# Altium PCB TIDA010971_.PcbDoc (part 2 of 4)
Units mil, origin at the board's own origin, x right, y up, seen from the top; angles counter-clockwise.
Board outline 4500 x 6000 mil, 2 copper layers (F.CU, B.CU), stack 60.617 mil thick; 280 components, 124 nets, 681 pads, 871 vias.
Unrouted connection lines stored in the file: 1.
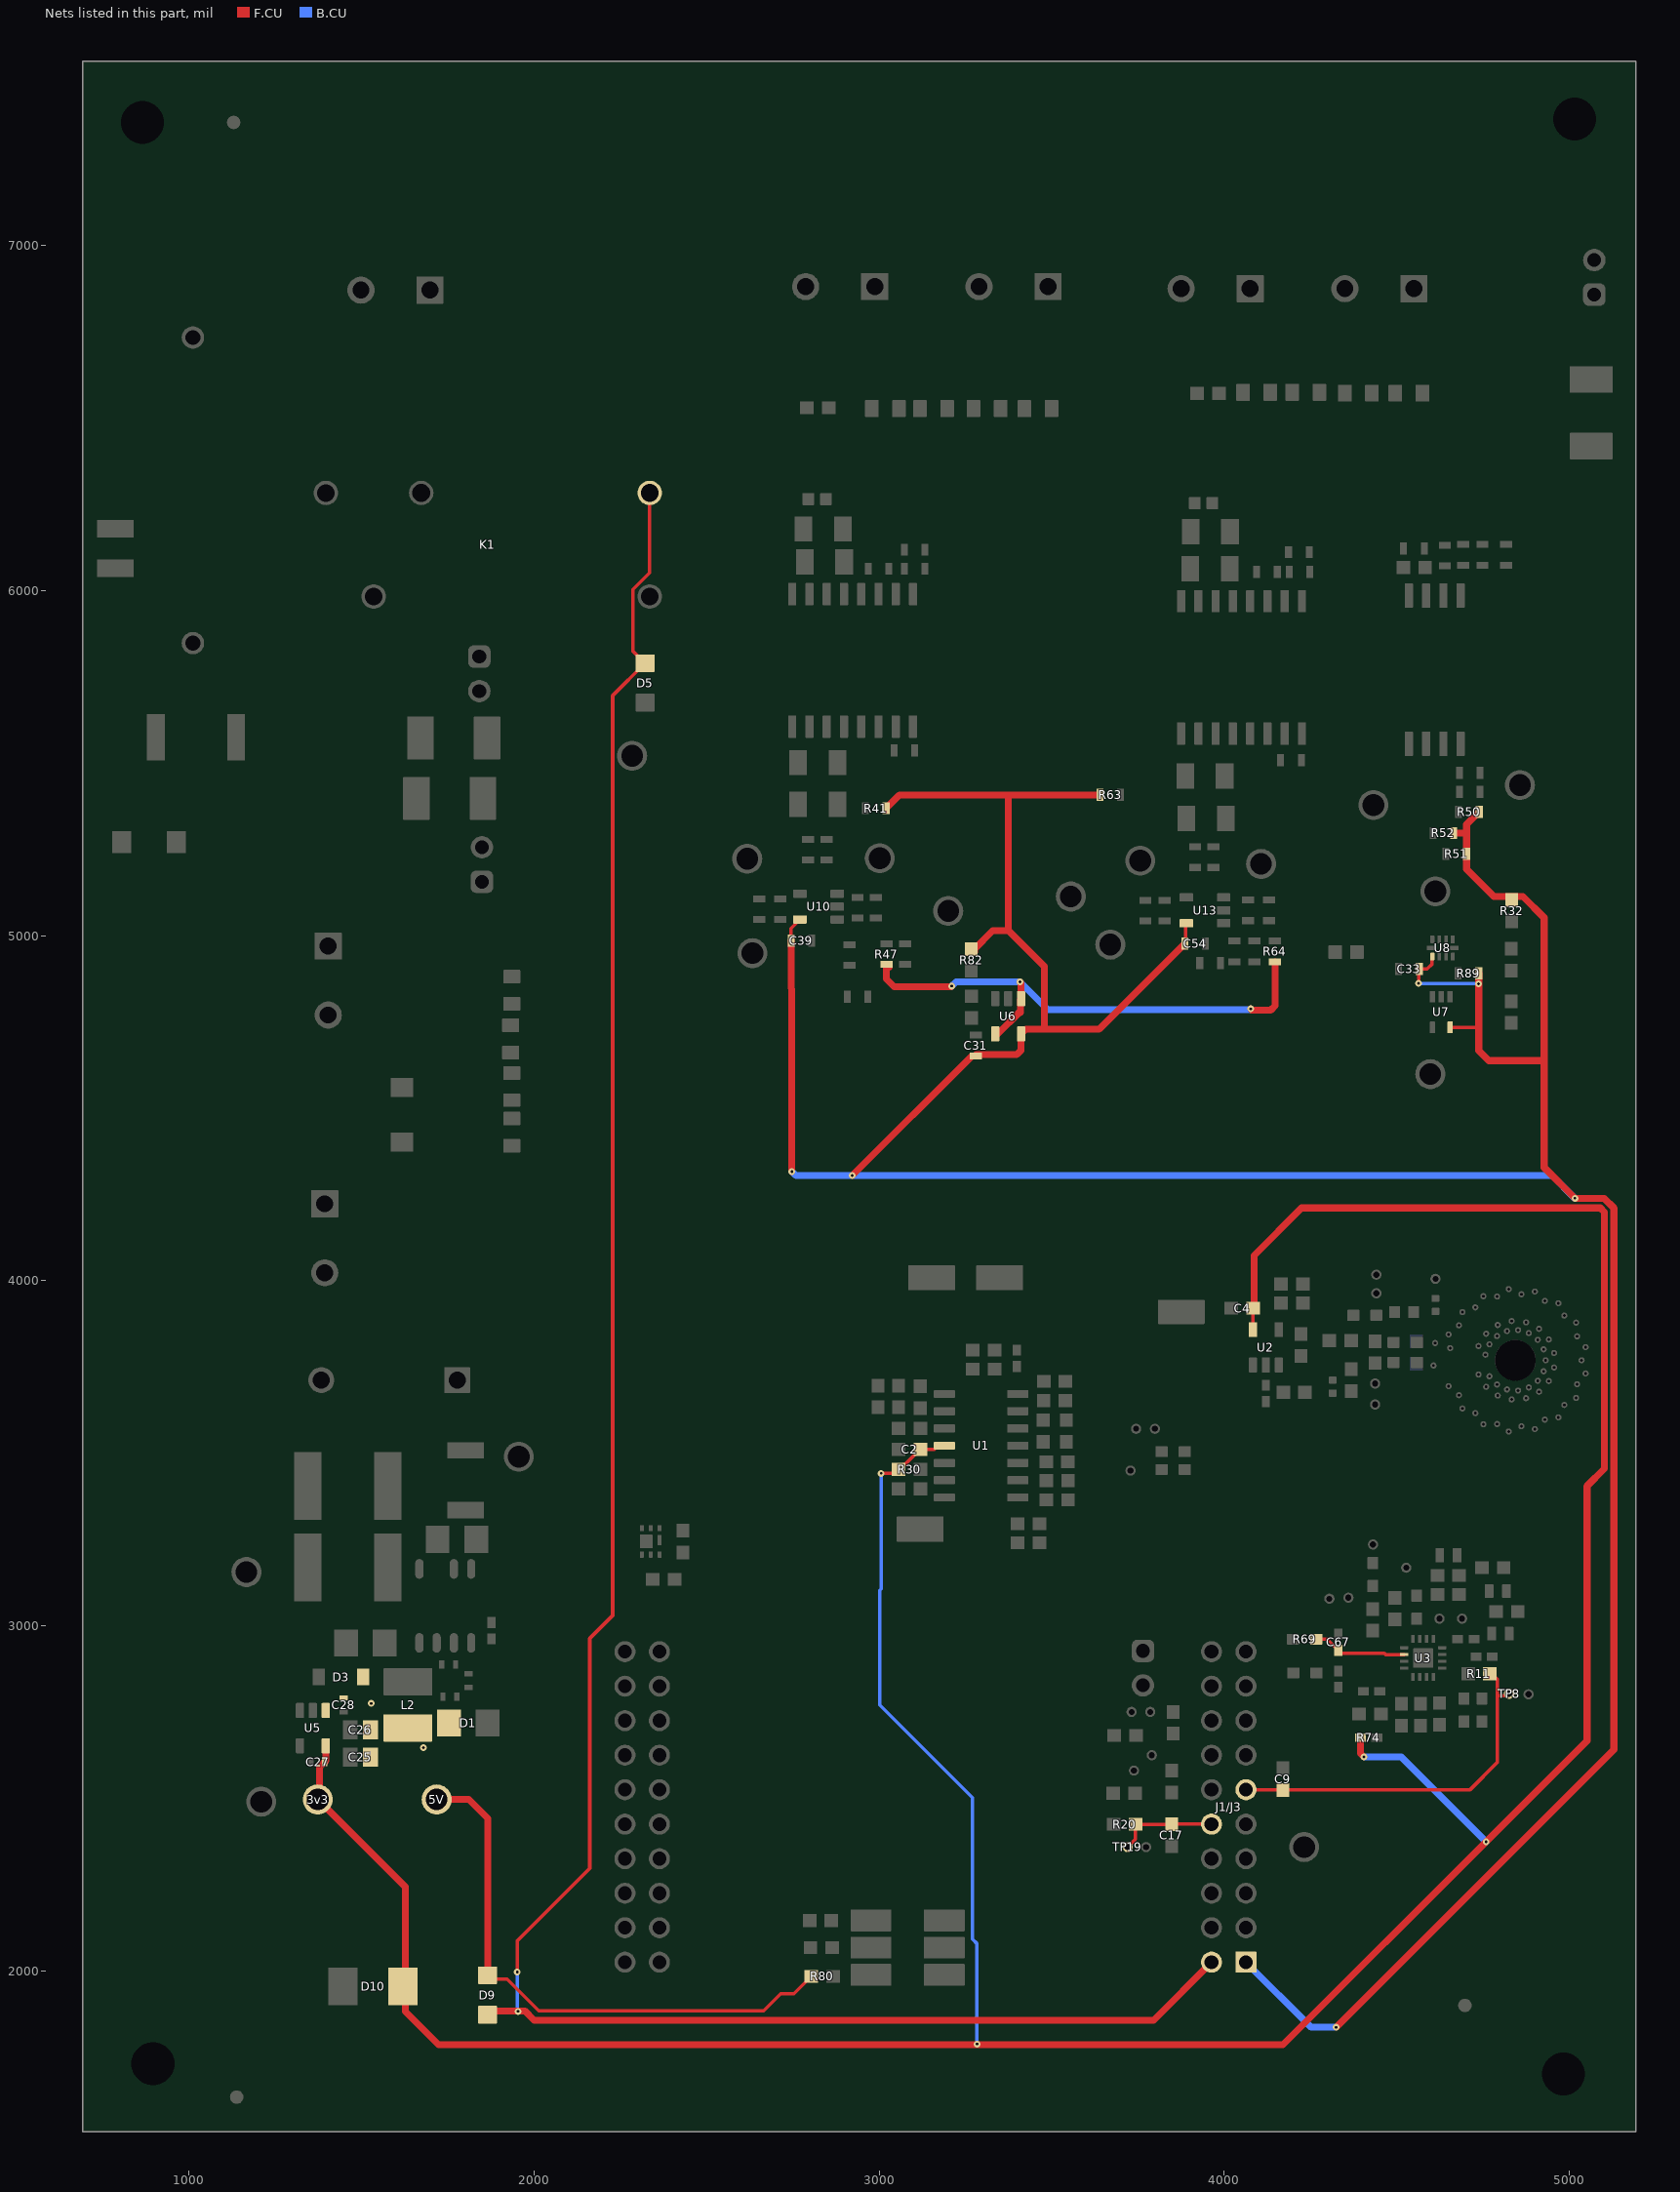
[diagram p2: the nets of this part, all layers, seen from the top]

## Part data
1 AGND3 TP_VIN: library part CMP-0089962-1, "Natural PC Test Point Brass, Tin Plating Surface Mount Mounting Type", Current_A=2A, Digikey Part Number=952-1478-1-ND, Manufacturer=Harwin, Mouser Part Number=855-S1751-46R, Operating Temperature Range="-55°C to +125°C"
3v3 5V Primary: library part CMP-0055147-2, "Test Point, Multipurpose, Red, TH", Color=Red, Manufacturer="Keystone Electronics", Supplier Part Number 1=36-5010-ND
AGND2: library part CMP-0055143-2, "Test Point, Compact, Black, TH", Color=Black, Manufacturer="Keystone Electronics", PartNumber=5006, Supplier Part Number 1=36-5006-ND
C1 C10: library part CMP-0007159-4, "CAP, CERM, 1000 pF, 25 V, +/- 5%, C0G/NP0, 0603", Cap_Case=0603, Manufacturer=MuRata, Supplier Part Number 1=GRM1885C1E102JA01D-ND, TempCo=C0G/NP0, Tolerance_%=5%, Value1=Unknown, Value2=25V, ValueDisplayed=1000pF
C2 C4 C13: library part CMP-0006815-4, "CAP, CERM, 0.1 uF, 10 V, +/- 10%, X7R, 0603", Cap_Case=0603, Manufacturer=AVX, Supplier Part Number 1=478-7939-1-ND, TempCo=X7R, Tolerance_%=10%, Value1=Unknown, Value2=10V, ValueDisplayed=0.1uF
C3 C32: library part CMP-0093200-1, "1µF ±10% 10V Ceramic Capacitor X7R 0402 (1005 Metric)", Digikey Part Number=2571-GMC04X7R105K10NTTR-ND, Manufacturer="Cal-Chip Electronics", Operating Temperature Range="-55°C to +125°C", TempCo=15%, Temperature Characteristic=X7R, Tolerance_%=10%, ValueDisplayed=1uF
C5 C11: library part CMP-0006910-4, "CAP, CERM, 270 pF, 50 V, +/- 5%, C0G/NP0, 0603", Cap_Case=0603, Manufacturer=Kemet, Supplier Part Number 1=399-1067-1-ND, TempCo=C0G/NP0, Tolerance_%=5%, Value1=Unknown, Value2=50V, ValueDisplayed=270pF
C6 C7 C19: library part CMP-0006763-4, "CAP, CERM, 100 pF, 50 V, +/- 5%, C0G/NP0, 0603", Cap_Case=0603, Manufacturer=AVX, Supplier Part Number 1=478-1175-1-ND, TempCo=C0G/NP0, Tolerance_%=5%, Value1="0.119 ohm", Value2=50V, ValueDisplayed=100pF
C8: library part CMP-0083854-1, "CAP, CERM, 0.1 µF, 50 V,+/- 5%, X7R, 0603", Cap_Case=0603, Manufacturer=AVX, TempCo=X7R, Tolerance_%=5%, Value2=50V, ValueDisplayed=0.1µF
C9 C17 C30: library part CMP-0007220-4, "CAP, CERM, 47 pF, 50 V, +/- 5%, C0G/NP0, 0603", Cap_Case=0603, Manufacturer=MuRata, Supplier Part Number 1=490-1419-1-ND, TempCo=C0G/NP0, Tolerance_%=5%, Value1=Unknown, Value2=50V, ValueDisplayed=47pF
C12: library part CMP-0007182-4, "CAP, CERM, 130 pF, 50 V, +/- 5%, C0G/NP0, 0603", Cap_Case=0603, Manufacturer=MuRata, Supplier Part Number 1=490-1430-1-ND, TempCo=C0G/NP0, Tolerance_%=5%, Value1=Unknown, Value2=50V, ValueDisplayed=130pF
C14: library part CMP-0007186-4, "CAP, CERM, 1500 pF, 50 V, +/- 5%, C0G/NP0, 0603", Cap_Case=0603, Manufacturer=MuRata, Supplier Part Number 1=490-1455-1-ND, TempCo=C0G/NP0, Tolerance_%=5%, Value1=Unknown, Value2=50V, ValueDisplayed=1500pF
C15: library part CMP-0006789-4, "CAP, CERM, 47 pF, 50 V, +/- 5%, C0G/NP0, 0603", Cap_Case=0603, Manufacturer=AVX, Supplier Part Number 1=478-1171-1-ND, TempCo=C0G/NP0, Tolerance_%=5%, Value1="0.174 ohm", Value2=50V, ValueDisplayed=47pF
C16 C70: library part CMP-0085576-2, "CAP, CERM, 3900 pF, 50 V,+/- 10%, X7R, 0402", Cap_Case=0402, Manufacturer="Samsung Electro-Mechanics", TempCo=X7R, Tolerance_%=10%, Value2=50V, ValueDisplayed=3900pF
C18: library part CMP-0007209-4, "CAP, CERM, 330 pF, 50 V, +/- 5%, C0G/NP0, 0603", Cap_Case=0603, Manufacturer=MuRata, Supplier Part Number 1=490-1439-1-ND, TempCo=C0G/NP0, Tolerance_%=5%, Value1=Unknown, Value2=50V, ValueDisplayed=330pF
C20: library part CMP-0006679-2, "CAP, CERM, 0.015 uF, 50 V, +/- 10%, X7R, 0402", Cap_Case=0402, Manufacturer=MuRata, Supplier Part Number 1=490-4517-1-ND, TempCo=X7R, Tolerance_%=10%, Value1=Unknown, Value2=50V, ValueDisplayed=0.015uF
C21: library part CMP-0084375-1, "CAP, CERM, 1 µF, 16 V,+/- 20%, X5R, 0402", Cap_Case=0402, Manufacturer=MuRata, TempCo=X5R, Tolerance_%=20%, Value2=16V, ValueDisplayed=1µF
C22 C23: library part CMP-0009428-2, "CAP, CERM, 2.2 uF, 450 V, +/- 20%, X7T, AEC-Q200 Grade 1, 6x5x5mm", Cap_Case=2220, Manufacturer=TDK, Supplier Part Number 1=445-7109-1-ND, TempCo=X7T, Tolerance_%=20%, Value1=Unknown, Value2=450V, ValueDisplayed=2.2uF
C24: library part CMP-0006449-2, "CAP, CERM, 2.4 pF, 50 V, +/- 5%, C0G/NP0, 0402", Cap_Case=0402, Manufacturer=MuRata, Supplier Part Number 1=81-GRM1555C1H2R4CA1D, TempCo=C0G/NP0, Tolerance_%=5%, Value1=Unknown, Value2=50V, ValueDisplayed=2.4pF
C25 C26: library part CMP-0078699-1, "CAP, CERM, 47 µF, 10 V,+/- 20%, X5R, 0805", Cap_Case=0805, Manufacturer=MuRata, Supplier Part Number 1=490-9961-1-ND, TempCo=X5R, Tolerance_%=20%, Value2=10V, ValueDisplayed=47µF
C27: library part CMP-0064927-2, "CAP, CERM, 1 uF, 10 V,+/- 20%, X5R, 0402", Cap_Case=0402, Manufacturer=MuRata, Supplier Part Number 1=490-5409-1-ND, TempCo=X5R, Tolerance_%=20%, Value1=Unknown, Value2=10V, ValueDisplayed=1uF
C28: library part CMP-0006562-2, "CAP, CERM, 0.1 uF, 10 V, +/- 10%, X5R, 0402", Cap_Case=0402, Manufacturer=MuRata, Supplier Part Number 1=490-1318-1-ND, TempCo=X5R, Tolerance_%=10%, Value1=Unknown, Value2=10V, ValueDisplayed=0.1uF
C29: library part CMP-0007109-5, "CAP, CERM, 0.01 uF, 50 V, +/- 10%, X7R, 0603", Cap_Case=0603, Manufacturer="Samsung Electro-Mechanics", Supplier Part Number 1=1276-1921-1-ND, TempCo=X7R, Tolerance_%=10%, Value1=Unknown, Value2=50V, ValueDisplayed=0.01uF
C31 C37 C38 C58 C59: library part CMP-0079602-1, "CAP, CERM, 0.1 µF, 50 V,+/- 10%, X7R, AEC-Q200 Grade 1, 0603", Cap_Case=0603, Manufacturer=Kemet, Supplier Part Number 1=399-6856-1-ND, TempCo=X7R, Tolerance_%=10%, Value2=50V, ValueDisplayed=0.1µF
C33: library part CMP-0006856-6, "CAP, CERM, 0.1 uF, 25 V, +/- 5%, X7R, 0603", Cap_Case=0603, Manufacturer=Kemet, Supplier Part Number 1=399-1282-1-ND, TempCo=X7R, Tolerance_%=5%, Value1=Unknown, Value2=25V, ValueDisplayed=0.1uF
C34 C47 C50 C55: library part CMP-0006754-4, "CAP, CERM, 1 uF, 25 V, +/- 10%, X7R, 0603", Cap_Case=0603, Manufacturer=AVX, Supplier Part Number 1=478-10046-1-ND, TempCo=X7R, Tolerance_%=10%, Value1=Unknown, Value2=25V, ValueDisplayed=1uF
C35 C56: library part CMP-0006847-4, "CAP, CERM, 1000 pF, 50 V, +/- 10%, X7R, 0603", Cap_Case=0603, Manufacturer=Kemet, Supplier Part Number 1=399-1082-1-ND, TempCo=X7R, Tolerance_%=10%, Value1=Unknown, Value2=50V, ValueDisplayed=1000pF
C36 C45 C46 C51 C57 C60: library part CMP-0007114-5, "CAP, CERM, 1000 pF, 50 V, +/- 5%, X7R, 0603", Cap_Case=0603, Manufacturer="Samsung Electro-Mechanics", Supplier Part Number 1=1276-1091-1-ND, TempCo=X7R, Tolerance_%=5%, Value1=Unknown, Value2=50V, ValueDisplayed=1000pF
C39 C54: library part CMP-0006855-4, "CAP, CERM, 0.1 uF, 25 V, +/- 5%, X7R, 0603", Cap_Case=0603, Manufacturer=Kemet, Supplier Part Number 1=1650833, TempCo=X7R, Tolerance_%=5%, Value1=Unknown, Value2=25V, ValueDisplayed=0.1uF
C40 C61: library part CMP-0045719-1, "1000 pF ±10% 50V Ceramic Capacitor X7R 0603 (1608 Metric)", Digikey Part Number=399-C0603X102K5RAC7867CT-ND, Manufacturer=KEMET, Mouser Part Number=80-C0603X102K5R, Operating Temperature Range="-55°C to +125°C", TempCo=15%, Temperature Characteristic=X7R, Tolerance_%=10%, ValueDisplayed=1000pF
C41 C43 C62 C64: library part CMP-0008530-2, "CAP, CERM, 1000 pF, 50 V, +/- 10%, X7R, 1206", Cap_Case=1206, Manufacturer=AVX, Supplier Part Number 1=478-1530-1-ND, TempCo=X7R, Tolerance_%=10%, Value1="0.427 ohm", Value2=50V, ValueDisplayed=1000pF
C42 C63: library part CMP-0008586-2, "CAP, CERM, 0.1 uF, 50 V, +/- 10%, X7R, 1206", Cap_Case=1206, Manufacturer=Kemet, Supplier Part Number 1=399-1249-1-ND, TempCo=X7R, Tolerance_%=10%, Value1="0.059 ohm", Value2=50V, ValueDisplayed=0.1uF
C44 C65: library part CMP-0008509-2, "CAP, CERM, 1 uF, 25 V, +/- 10%, X7R, 1206", Cap_Case=1206, Manufacturer=AVX, Supplier Part Number 1=478-1567-1-ND, TempCo=X7R, Tolerance_%=10%, Value1="0.013 ohm", Value2=25V, ValueDisplayed=1uF
C48 C49 C53: library part CMP-0006753-4, "CAP, CERM, 0.1 uF, 25 V, +/- 10%, X7R, 0603", Cap_Case=0603, Manufacturer=AVX, Supplier Part Number 1=478-3714-1-ND, TempCo=X7R, Tolerance_%=10%, Value1="0.05 ohm", Value2=25V, ValueDisplayed=0.1uF
C52: library part CMP-0006839-4, "CAP, CERM, 10 pF, 50 V, +/- 5%, C0G/NP0, 0603", Cap_Case=0603, Manufacturer=Kemet, Supplier Part Number 1=399-1049-1-ND, TempCo=C0G/NP0, Tolerance_%=5%, Value1=Unknown, Value2=50V, ValueDisplayed=10pF
C66 C67: library part CMP-0860544-1, "CAP, CERM, 0.01 µF, 6.3 V,+/- 10%, X7R, 0402", Cap_Case=0402, Manufacturer=Walsin, TempCo=X7R, Tolerance_%=10%, Value2=6.3V, ValueDisplayed=0.01µF
C68: library part CMP-0007497-5, "CAP, CERM, 10 uF, 10 V, +/- 20%, X7R, 0603", Cap_Case=0603, Manufacturer=MuRata, Supplier Part Number 1=81-GRM188Z71A106MA3D, TempCo=X7R, Tolerance_%=20%, Value1=Unknown, Value2=10V, ValueDisplayed=10uF
C69: library part CMP-0006622-2, "CAP, CERM, 0.01 uF, 6.3 V, +/- 10%, X7R, 0402", Cap_Case=0402, Manufacturer=MuRata, Supplier Part Number 1=GRM155R70J103KA01D-ND, TempCo=X7R, Tolerance_%=10%, Value1=Unknown, Value2=6.3V, ValueDisplayed=0.01uF
C71: library part CMP-0077664-2, "CAP, Film, 0.1 µF, X2 305 VAC, +/- 10%, AEC-Q200 Grade 2, TH", Manufacturer=TDK, Supplier Part Number 1=495-4355-ND, Tolerance_%=10%, ValueDisplayed=0.1µF
C72: library part CMP-0081059-1, "CAP, CERM, 1000 pF, 25 V,+/- 5%, C0G/NP0, 0402", Cap_Case=0402, Manufacturer=Kemet, Supplier Part Number 1=399-7751-1-ND, TempCo=C0G/NP0, Tolerance_%=5%, Value2=25V, ValueDisplayed=1000pF
CTR: library part CMP-0055142-2, "Test Point, Compact, Red, TH", Color=Red, Manufacturer="Keystone Electronics", PartNumber=5005, Supplier Part Number 1=36-5005-ND
D1 D2 D4: library part CMP-0029015-1, "Diode, Ultrafast, 600 V, 1 A, 1408 Diode", Manufacturer=Bourns, Supplier Part Number 1=CD1408-FU1600CT-ND, Value1=1A, Value2=1.25V
D3: library part CMP-0085110-1, "Diode, Zener, 8.2 V, 500 mW, SOD-123", Manufacturer="Diodes Inc.", Power_W=500mW, Value1=0.5W
D5 D9: library part CMP-0028636-3, "Diode, Schottky, 20 V, 1.1 A, DO-219AB", Manufacturer=Vishay-Semiconductor, PartNumber=SL02-GS08, Value1=1.1A, Value2=0.42V
D6: library part CMP-0078806-2, "LED, RGB, SMD", Color=RGB, Manufacturer=Kingbright, Power_TotalModule=350mW, Value1=0.35W, Value2=3.3V
D7 D8: library part CMP-0085045-1, "Diode, TVS, Bi, 400 V, 648 Vc, 400 W, 0.6 A, SMA (non-polarized)", Manufacturer=Littelfuse, Value1=648V
D10: library part CMP-0005592-3, "Diode, TVS, Uni, 3.3 V, 7.3 Vc, AEC-Q101, SMB", Manufacturer=Vishay-Semiconductor, Value1=600W
F1 F2 F3: library part CMP-0121481-1, "5 A 250 V AC 125 V DC Fuse Board Mount (Cartridge Style Excluded) Surface Mount 2-SMD, Square End Block", Digikey Part Number=F6636CT-ND, Fuse Current=5A, Fuse Interrupt Dc Current=300A, Manufacturer=Littelfuse, Mouser Part Number=576-0476005.MR, Operating Temperature Range="-55°C to +125°C"
FID1 FID2 FID3: library part CMP-0077181-1, "Fiducial mark.  There is nothing to buy or mount.", Manufacturer=N/A
GND Neutral: library part CMP-0055148-2, "Test Point, Multipurpose, Black, TH", Color=Black, Manufacturer="Keystone Electronics", Supplier Part Number 1=36-5011-ND
J1 J7 J12 J13: library part CMP-0075405-2, "Header, 100mil, 2x1, Gold, TH", Color=Black, Current_A=6.3A, Manufacturer=Samtec, Supplier Part Number 1=SAM1029-02-ND, Voltage_V=550V
J1/J3: library part CMP-0003837-4, "Receptacle, 2.54mm, 10x2, Tin, TH", Alternate Manufacturer="Major League Electronics", Alternate PartNumber=CRD-081413-A-G, Manufacturer=Samtec, Supplier Part Number 1=SAM1204-10-ND
J2 J3 J4 J5 J6 J8 J9: library part CMP-0074910-1, "Terminal Block, 5.08 mm, 2x1, Brass, TH", Color=Blue, Current_A=15A, Manufacturer="On-Shore Technology", Supplier Part Number 1=ED1609-ND, Voltage_V=300V
J2/J4: library part CMP-0078266-4, "Receptacle, 2.54mm, 10x2, Tin, TH", Alternate Manufacturer="Major League Electronics", Alternate PartNumber=CRD-081413-A-G, Manufacturer=Samtec, Supplier Part Number 1=SAM1204-10-ND
K1: library part CMP-0002574-2, "Relay, SPDT ( 1 Form C), 12 A, 5 V, TH", Coil Current_A=80mA, Coil Power_W=403mW, Coil Resistance_ohm=62, Coil Voltage_VDC=5V, Contact Rating_A=12A, Manufacturer="Tyco Electronics", Supplier Part Number 1=PB359-ND, Turn Off Voltage (Min)_VDC=5dV, Turn On Voltage (Max)_VDC=3.5V
L1: library part CMP-0058731-1, "Inductor, Multilayer, Ferrite, 10 uH, 0.05 A, 0.9 ohm, SMD", Manufacturer=MuRata, Supplier Part Number 1=490-4025-1-ND, Value1="0.9 ohm", Value2=0.05A, ValueDisplayed=10uH
L2: library part CMP-0084743-1, "Inductor, Wirewound, Ferrite, 680 µH, 0.09 A, 16.8 ohm, SMD", Manufacturer="Wurth Elektronik", Value1="16.8 ohm", Value2=0.09A, ValueDisplayed=680µH
L3: library part CMP-0060129-1, "Inductor, Wirewound, Ferrite, 820 nH, 0.42 A, 0.579999 ohm, SMD", Manufacturer=Coilcraft, Value1="0.579999 ohm", Value2=0.42A, ValueDisplayed=820nH
L4: library part CMP-0077489-1, "Inductor, Wirewound, Ferrite, 3.9 µH, 0.28 A, 1.6 ohm, AEC-Q200 Grade 3, SMD", Manufacturer=Coilcraft, Supplier Part Number 1=994-0603LS-392XJLB, Value1="1.6 ohm", Value2=0.28A, ValueDisplayed=3.9µH
L5: library part CMP-0077486-1, "Inductor, Wirewound, Ferrite, 330 nH, 0.56 A, 0.46 ohm, AEC-Q200 Grade 3, SMD", Manufacturer=Coilcraft, Supplier Part Number 1=994-0603LS-331XJLB, Value1="0.46 ohm", Value2=0.56A, ValueDisplayed=330nH
Logo1: library part CMP-0074838-1, "Texas Instrument Corporate Signature"
Logo2: library part CMP-0074844-1
Logo3: library part CMP-0074847-1, "FCC_disclaimer"
Logo4: library part CMP-0074769-1
LOGO5 LOGO6 LOGO8 LOGO10: library part CMP-0074835-1, "IEC 61010-1 High Voltage Warning"
LOGO7 LOGO9: library part CMP-0074837-1, "IEC 61010-1 Hot Surface Warning"
MH1 MH2 MH3 MH4: library part CMP-0078424-2, "PCB Mounting Hole, No Pad", Manufacturer=Any, PartNumber=N/A
MP1 MP2 MP3 MP4: library part CMP-0122442-1, "Hex Standoff Threaded #4-40 Nylon 1.000\" (25.40mm) 1\" Natural", Digikey Part Number=36-4806-ND, Manufacturer=Keystone, Mouser Part Number=534-4806, Operating Temperature Range=to
Q1: library part CMP-0000193-1, "MOSFET, N-CH, 12 V, 22 A, DQK0006C (WSON-6)", Alternate Manufacturer=None, Manufacturer="Texas Instruments", Supplier Part Number 1=CSD13202Q2-ND, Value1=0.009, Value2="5.1 nC"
R1: library part CMP-0023953-2, "RES, 221, 0.1%, 0.1 W, 0603", Manufacturer="Yageo America", Power_W=100mW, TempCo="25 ppm/C", Tolerance_%=0.1%, Value2=0.1W, Value_Code=221R, ValueDisplayed=221
R2 R4: library part CMP-0022004-4, "RES, 10.0, 1%, 0.25 W, AEC-Q200 Grade 0, 0603", Manufacturer=Vishay-Dale, Power_W=250mW, Supplier Part Number 1=541-10.0SCT-ND, TempCo="100 ppm/C", Tolerance_%=1%, Value2=0.25W, Value_Code=10R0, ValueDisplayed=10.0
R3: library part CMP-0023468-3, "RES, 221, 0.1%, 0.1 W, 0603", Manufacturer="Susumu Co Ltd", Power_W=100mW, Supplier Part Number 1=RG16P221BCT-ND, TempCo="25 ppm/C", Tolerance_%=0.1%, Value2=0.1W, Value_Code=221R, ValueDisplayed=221
R5: library part CMP-0025335-3, "RES, 4.02 k, 0.5%, 0.1 W, 0603", Manufacturer="Yageo America", Power_W=100mW, TempCo="50 ppm/C", Tolerance_%=0.5%, Value2=0.1W, Value_Code=4k02, ValueDisplayed=4.02k
R6: library part CMP-0024341-3, "RES, 562 k, 0.1%, 0.1 W, 0603", Manufacturer="Yageo America", Power_W=100mW, TempCo="25 ppm/C", Tolerance_%=0.1%, Value2=0.1W, Value_Code=562k
R7: library part CMP-0023646-2, "RES, 10.1 k, 0.1%, 0.1 W, 0603", Manufacturer="Yageo America", Power_W=100mW, TempCo="25 ppm/C", Tolerance_%=0.1%, Value2=0.1W, Value_Code=10k1, ValueDisplayed=10.1k
R8: library part CMP-0022694-3, "RES, 27.0 k, 1%, 0.1 W, AEC-Q200 Grade 0, 0603", Manufacturer=Panasonic, Power_W=100mW, Supplier Part Number 1=P27.0KHCT-ND, TempCo="100 ppm/C", Tolerance_%=1%, Value2=0.1W, Value_Code=27k0, ValueDisplayed=27.0k
R9: library part CMP-0022961-4, "RES, 270 k, 1%, 0.1 W, 0603", Manufacturer=Yageo, Power_W=100mW, Supplier Part Number 1=311-270KHRCT-ND, TempCo="100 ppm/C", Tolerance_%=1%, Value2=0.1W, Value_Code=270k
R10 R25 R30 R81 R82: library part CMP-0082530-1, "RES, 100 k, 5%, 0.1 W, 0603", Manufacturer=Vishay-Dale, Power_W=100mW, Supplier Part Number 1=541-3992-1-ND, TempCo="200 ppm/C", Tolerance_%=5%, Value2=0.1W, Value_Code=100k
R11 R20: library part CMP-0023567-3, "RES, 510, 0.1%, 0.1 W, 0603", Manufacturer="Susumu Co Ltd", Power_W=100mW, Supplier Part Number 1=RG16P510BCT-ND, TempCo="25 ppm/C", Tolerance_%=0.1%, Value2=0.1W, Value_Code=510R, ValueDisplayed=510
R12 R13 R14 R16 R37 R38 R39 R40 R57 R58 R60 R62: library part CMP-0021166-3, "RES, 316 k, 1%, 0.125 W, AEC-Q200 Grade 0, 0805", Manufacturer=Vishay-Dale, Power_W=125mW, Supplier Part Number 1=541-316KCCT-ND, TempCo="100 ppm/C", Tolerance_%=1%, Value2=0.125W, Value_Code=316k
R15: library part CMP-0023020-5, "RES, 30.0 k, 1%, 0.1 W, 0603", Manufacturer=Yageo, Power_W=100mW, Supplier Part Number 1=311-30.0KHRCT-ND, TempCo="100 ppm/C", Tolerance_%=1%, Value2=0.1W, Value_Code=30k0, ValueDisplayed=30.0k
R17: library part CMP-0025488-3, "RES, 64.9 k, 0.5%, 0.1 W, 0603", Manufacturer="Yageo America", Power_W=100mW, TempCo="50 ppm/C", Tolerance_%=0.5%, Value2=0.1W, Value_Code=64k9, ValueDisplayed=64.9k
R18 R22: library part CMP-0025730-4, "RES, 1.1 k, 5%, 0.1 W, AEC-Q200 Grade 0, 0603", Manufacturer=Vishay-Dale, Power_W=100mW, Supplier Part Number 1=541-1.1KGCT-ND, TempCo="200 ppm/C", Tolerance_%=5%, Value2=0.1W, Value_Code=1k10, ValueDisplayed=1.1k
R19: library part CMP-0023215-5, "RES, 619, 1%, 0.1 W, 0603", Manufacturer=Yageo, Power_W=100mW, Supplier Part Number 1=311-619HRCT-ND, TempCo="100 ppm/C", Tolerance_%=1%, Value2=0.1W, Value_Code=619R, ValueDisplayed=619
R21 R35 R67 R68 R69 R70 R73 R75 R84 R86 R87: library part CMP-0123755-1, "0 Ohms Jumper Chip Resistor 0603 (1608 Metric) Moisture Resistant Thick Film", Digikey Part Number=13-RC0603FR-100RLCT-ND, Manufacturer=Yageo, Mouser Part Number=603-RC0603FR-100RL, Operating Temperature Range="-55°C to +155°C", Tolerance_%=1%
R23: library part CMP-0023253-5, "RES, 6.80 k, 1%, 0.1 W, 0603", Manufacturer=Yageo, Power_W=100mW, Supplier Part Number 1=311-6.80KHRCT-ND, TempCo="100 ppm/C", Tolerance_%=1%, Value2=0.1W, Value_Code=6k80, ValueDisplayed=6.80k
R24: library part CMP-0023577-3, "RES, 56.0 k, 0.1%, 0.1 W, 0603", Manufacturer="Susumu Co Ltd", Power_W=100mW, Supplier Part Number 1=RG16P56.0KBCT-ND, TempCo="25 ppm/C", Tolerance_%=0.1%, Value2=0.1W, Value_Code=56k0, ValueDisplayed=56.0k
R26: library part CMP-0026323-1, "RES, 38.3 k, 1%, 0.063 W, 0402", Manufacturer=Vishay-Dale, Power_W=63mW, Supplier Part Number 1=541-38.3KLCT-ND, TempCo="100 ppm/C", Tolerance_%=1%, Value2=0.063W, Value_Code=38k3, ValueDisplayed=38.3k
R27: library part CMP-0016409-3, "RES, 470, 1%, 0.75 W, AEC-Q200 Grade 0, 2010", Manufacturer=Vishay-Dale, Power_W=750mW, Supplier Part Number 1=541-470ACCT-ND, TempCo="100 ppm/C", Tolerance_%=1%, Value2=0.75W, Value_Code=470R, ValueDisplayed=470
R28: library part CMP-0026658-1, "RES, 10.0 k, 1%, 0.1 W, 0402", Manufacturer=Panasonic, Power_W=100mW, Supplier Part Number 1=P10.0KLCT-ND, TempCo="100 ppm/C", Tolerance_%=1%, Value2=0.1W, Value_Code=10k0, ValueDisplayed=10.0k
R29: library part CMP-0092774-1, "430 V 6.5 kA Varistor 1 Circuit Through Hole Disc 20mm", Clamping Voltage=710V, Digikey Part Number=MOV-20D431K-ND, Manufacturer="Bourns Inc.", Mouser Part Number=652-MOV-20D431K, Operating Temperature Range="-40°C to +105°C", ValueDisplayed=1116pF, Varistor Voltage=387V, Voltage Tolerance=10%
R31: library part CMP-0023238-5, "RES, 68.1 k, 1%, 0.1 W, 0603", Manufacturer=Yageo, Power_W=100mW, Supplier Part Number 1=311-68.1KHRCT-ND, TempCo="100 ppm/C", Tolerance_%=1%, Value2=0.1W, Value_Code=68k1, ValueDisplayed=68.1k
R32 R88: library part CMP-0080488-1, "RES, 10.0 k, 1%, 0.1 W, 0603", Manufacturer="TT Electronics/IRC", Power_W=100mW, TempCo="100 ppm/C", Tolerance_%=1%, Value2=0.1W, Value_Code=10k0, ValueDisplayed=10.0k
R33: library part CMP-0094956-1, "0 Ohms Jumper 0.1W, 1/10W Chip Resistor 0603 (1608 Metric) - Thick Film", Digikey Part Number=2679-CR0603-10W-000TTR-ND, Manufacturer=Venkel, Operating Temperature Range="-55°C to +155°C", Power_W=100mW
R34: library part CMP-0023318-5, "RES, 91.0 k, 1%, 0.1 W, 0603", Manufacturer=Yageo, Power_W=100mW, Supplier Part Number 1=311-91.0KHRCT-ND, TempCo="100 ppm/C", Tolerance_%=1%, Value2=0.1W, Value_Code=91k0, ValueDisplayed=91.0k
R36 R46 R53 R61: library part CMP-0023800-3, "RES, 16.5 k, 0.1%, 0.1 W, 0603", Manufacturer="Yageo America", Power_W=100mW, TempCo="25 ppm/C", Tolerance_%=0.1%, Value2=0.1W, Value_Code=16k5, ValueDisplayed=16.5k
R41 R49 R50 R63: library part CMP-0025885-5, "RES, 0, 5%, 0.1 W, 0603", Manufacturer=Yageo, Power_W=100mW, Supplier Part Number 1=311-0.0GRCT-ND, TempCo="200 ppm/C", Tolerance_%=5%, Value2=0.1W, Value_Code=0000, ValueDisplayed=0
R42 R66: library part CMP-0023079-5, "RES, 3.24 k, 1%, 0.1 W, 0603", Manufacturer=Yageo, Power_W=100mW, Supplier Part Number 1=311-3.24KHRCT-ND, TempCo="100 ppm/C", Tolerance_%=1%, Value2=0.1W, Value_Code=3k24, ValueDisplayed=3.24k
R43 R45 R55 R59: library part CMP-0023653-3, "RES, 10.0 k, 0.1%, 0.1 W, 0603", Manufacturer="Yageo America", Power_W=100mW, TempCo="25 ppm/C", Tolerance_%=0.1%, Value2=0.1W, Value_Code=10k0, ValueDisplayed=10.0k
R44 R56: library part CMP-0025703-4, "RES, 10, 5%, 0.1 W, AEC-Q200 Grade 0, 0603", Manufacturer=Vishay-Dale, Power_W=100mW, Supplier Part Number 1=541-10GCT-ND, TempCo="200 ppm/C", Tolerance_%=5%, Value2=0.1W, Value_Code=10R0, ValueDisplayed=10
R47 R48 R64 R65: library part CMP-0023343-3, "RES, 0, 1%, 0.1 W, AEC-Q200 Grade 0, 0603", Manufacturer="Stackpole Electronics Inc", Power_W=100mW, Supplier Part Number 1=RMCF0603ZT0R00CT-ND, TempCo=ppm/C, Tolerance_%=1%, Value2=0.1W, Value_Code=0
R51 R52 R89: library part CMP-0025927-5, "RES, 4.7 k, 5%, 0.1 W, 0603", Manufacturer=Yageo, Power_W=100mW, Supplier Part Number 1=311-4.7KGRCT-ND, TempCo="100 ppm/C", Tolerance_%=5%, Value2=0.1W, Value_Code=4k70, ValueDisplayed=4.7k
R54: library part CMP-0025909-5, "RES, 2.0 k, 5%, 0.1 W, 0603", Manufacturer=Yageo, Power_W=100mW, Supplier Part Number 1=311-2.0KGRCT-ND, TempCo="100 ppm/C", Tolerance_%=5%, Value2=0.1W, Value_Code=2k00, ValueDisplayed=2.0k
R71: library part CMP-0078952-1, "RES, 200, 1%, 2 W, 2512", Manufacturer=Bourns, Power_W=2W, Supplier Part Number 1=CRM2512-FX-2000ELF-ND, TempCo="100 ppm/C", Tolerance_%=1%, Value_Code=200R, ValueDisplayed=200
R72: library part CMP-0083544-1, "RES, 3.3 M, 5%, 0.5 W, 1210", Manufacturer=Yageo, Power_W=500mW, TempCo="100 ppm/C", Tolerance_%=5%, Value2=0.5W, Value_Code=3M30, ValueDisplayed=3.3M
R74: library part CMP-0026717-1, "RES, 10.0, 1%, 0.063 W, 0402", Manufacturer=Rohm, Power_W=63mW, Supplier Part Number 1=RHM10.0LCT-ND, TempCo="100 ppm/C", Tolerance_%=1%, Value2=0.063W, Value_Code=10R0, ValueDisplayed=10.0
R76: library part CMP-0024583-2, "RES, 10.6 k, 0.5%, 0.1 W, 0603", Manufacturer="Yageo America", Power_W=100mW, TempCo="50 ppm/C", Tolerance_%=0.5%, Value2=0.1W, Value_Code=10k6, ValueDisplayed=10.6k
R77: library part CMP-0025893-5, "RES, 1.1 k, 5%, 0.1 W, 0603", Manufacturer=Yageo, Power_W=100mW, Supplier Part Number 1=311-1.1KGRCT-ND, TempCo="100 ppm/C", Tolerance_%=5%, Value2=0.1W, Value_Code=1k10, ValueDisplayed=1.1k
R78 R79 R80: library part CMP-0025930-5, "RES, 560, 5%, 0.1 W, 0603", Manufacturer=Yageo, Power_W=100mW, Supplier Part Number 1=311-560GRCT-ND, TempCo="100 ppm/C", Tolerance_%=5%, Value2=0.1W, Value_Code=560R, ValueDisplayed=560
R83: library part CMP-0023024-4, "RES, 316 k, 1%, 0.1 W, 0603", Manufacturer=Yageo, Power_W=100mW, Supplier Part Number 1=311-316KHRCT-ND, TempCo="100 ppm/C", Tolerance_%=1%, Value2=0.1W, Value_Code=316k
R85: library part CMP-0022220-4, "RES, 22.1 k, 1%, 0.1 W, AEC-Q200 Grade 0, 0603", Manufacturer=Vishay-Dale, Power_W=100mW, Supplier Part Number 1=541-22.1KHCT-ND, TempCo="100 ppm/C", Tolerance_%=1%, Value2=0.1W, Value_Code=22k1, ValueDisplayed=22.1k
SH-J1 SH-J5 SH-J6: library part CMP-0003641-1, "Shunt, 2mm, Gold plated, Black", Manufacturer=Samtec, Supplier Part Number 1=SAM8748-ND
TP1 TP2 TP3 TP4 TP5 TP6 TP7 TP8 TP9 TP10 TP11 TP12 TP13 TP15 TP17 TP18 TP19 TP20 TP22 TP24 TP25 TP26: library part CMP-0003719-1, "Testpoint", Manufacturer="Texas Instruments"
TP14 TP16 TP21 TP23 TP_AE TP_AGND1 TP_AGND2 TP_AGND3 TP_Cgap TP_Latch TP_Vgap TP_VSTRING: library part CMP-0055144-2, "Test Point, Compact, White, TH", Color=White, Manufacturer="Keystone Electronics", Supplier Part Number 1=36-5007-ND
TP_AGND: library part CMP-0078225-3, "PC Test Point, SMT", Manufacturer="Keystone Electronics", Supplier Part Number 1=36-5017CT-ND
U1: library part CMP-0125179-1, "Quad 5-MHz, 15-V/µs high slew-rate, RRIO op amp 14-SOIC -40 to 125", Digikey Part Number=296-53556-1-ND, Input Bias Current=2pA, Input Offset Voltage=0.33mV, Manufacturer="Texas Instruments", Max Dual Supply Voltage=3V, Max Supply Voltage=6V, Min Dual Supply Voltage=900mV, Min Supply Voltage=1.8V, Mouser Part Number=595-TLV9054IDR, Nominal Supply Current=330uA, Operating Temperature Range="-40°C to +125°C", Output Current Per Channel=50mA, Voltage Gain=130dB
U2: library part CMP-0125353-1, "Zero-Drift Amplifier 1 Circuit Rail-to-Rail SOT-23-5", Digikey Part Number=296-TLV387DBVRCT-ND, Input Bias Current=60pA, Input Offset Voltage=1.25uV, Manufacturer="Texas Instruments", Max Dual Supply Voltage=2.75V, Max Supply Voltage=5.5V, Min Dual Supply Voltage=850mV, Min Supply Voltage=1.7V, Mouser Part Number=595-TLV387DBVR, Nominal Supply Current=570uA, Operating Temperature Range="-40°C to +125°C", Output Current Per Channel=55mA, Voltage Gain=145dB
U3: library part CMP-0122050-1, "80-MHz, Logarithmic Detector With Integrated Low-Noise Amplifier", Manufacturer="Texas Instruments", Max Supply Voltage=5.25V, Min Supply Voltage=3V, Operating Temperature Range="-40°C to +125°C"
U4: library part CMP-0074092-2, "700-V Lowest Quiescent Current Off-Line Switcher, D0007A (SOIC-7)", Alternate Manufacturer="Texas Instruments", Alternate PartNumber=UCC28881D
U5: library part CMP-0034271-1, "150-mA 30-V low-dropout (LDO) linear regulator with 3.2-μA supply current 5-SOT-23 -40 to 125", Digikey Part Number=296-TLV709A33DBVRCT-ND, Dropout Voltage=1000mV, Manufacturer="Texas Instruments", Max Supply Voltage=30V, Min Supply Voltage=4.3V, Mouser Part Number=595-TLV709A33DBVR, Nominal Supply Current=3.2uA, Operating Temperature Range="-40°C to +125°C", Output Voltage=3.3V
U6: library part CMP-0090312-1, "General Purpose Amplifier 1 Circuit Rail-to-Rail SOT-23-5", Digikey Part Number=296-TLV9051IDBVRCT-ND, Input Bias Current=0.000002uA, Input Offset Voltage=0.33mV, Manufacturer="Texas Instruments", Max Supply Voltage=5.5V, Min Supply Voltage=1.8V, Mouser Part Number=595-TLV9051IDBVR, Nominal Supply Current=330uA, Operating Temperature Range="-40°C to +125°C", Output Current Per Channel=50mA, Voltage Gain=104dB
U7: library part CMP-0051644-4, "Single Schmitt-Trigger Inverter, DCK0005A (SOT-SC70-5)", Alternate Manufacturer="Texas Instruments", Alternate PartNumber=SN74LVC1G14DCKR, F @ Nom Voltage(Max)(Mhz)=150, Generic Part Number=SN74LVC1G14, ICC @ Nom Voltage(Max)(mA)=0.01, Operating Temperature Range="-40 to 125 C", Rating=Catalog, tpd @ Nom Voltage(Max)(ns)=11,6.5,5.5,5, Voltage(Nom)(V)=1.8,2.5,3.3,5
U8: library part CMP-0122167-3, "Precision, Self-Latching Comparator", Input Bias Current=0.000005uA, Input Offset Voltage=0.3mV, Manufacturer="Texas Instruments", Max Supply Voltage=5.5V, Min Supply Voltage=1.65V, Nominal Supply Current=20uA, Operating Temperature Range="-40°C to +125°C", Output Current Per Channel=100mA
U9 U12: library part CMP-0088720-4, "Precision, ±1-V Input, Reinforced Isolated Amplifier With Integrated DC/DC Converter", Manufacturer="Texas Instruments", Max Supply Voltage=5.5V, Min Supply Voltage=3V, Nominal Supply Current=27.5-28.5mA, Operating Temperature Range="-40°C to +125°C"
U10 U13: library part CMP-0073547-1, "1-MHz, Low-Power Operational Amplifier for Cost-Sensitive Systems, DBV0005A (SOT-23-5)", Alternate Manufacturer="Texas Instruments", Alternate PartNumber=TLV6001IDBVT
U11: library part CMP-0092823-1, "High-Speed Reinforced Comparator w/ Reference, Open-Drain and Push-Pull Output", Manufacturer="Texas Instruments", Operating Temperature Range=to
ZZ1: library part CMP-0003616-3
ZZ2: library part CMP-0077236-1
ZZ3: library part CMP-0077237-1
ZZ4: library part CMP-0077238-1

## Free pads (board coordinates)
  rect 37.4x39.37 smd far side: 1(4556.56,3824.28) 2(4556.56,3759.32)
  round 17.72 hole 7.87 paste-99999 mask-17.72: 3(4606.05,3754.35) 4(4610.86,3819.33) 12(4756.68,3785.66) 13(4654.31,3804.8) 14(4736.64,3810.76) 15(4649.88,3844.37) 16(4768.36,3815.82) 17(4679.82,3870.63) 18(4758.74,3846.46) 19(4689.98,3909.14) 20(4790.14,3839.71) 21(4727.39,3922.81) 22(4792.25,3871.76) 23(4750.77,3955.05) 24(4819.09,3854.13) 25(4790.59,3954.29) 26(4832.63,3883.25) 27(4824.04,3975.89) 28(4851.29,3857.11) 29(4860.9,3960.8) 30(4874.43,3879.38) 31(4899.9,3968.86) 32(4882.39,3848.26) 33(4928.81,3941.48) 34(4912.02,3860.66) 35(4968.09,3934.91) 36(4908.2,3828.77) 37(4985.15,3898.93) 38(4940.3,3829.64) 39(5019.41,3878.61) 40(4925.22,3801.28) 41(5022.32,3838.9) 42(4955.47,3790.49) 43(5046.92,3807.58) 44(4931.16,3769.49) 45(5035.3,3769.49) 46(4955.47,3748.5) 47(5046.92,3731.41) 48(4925.22,3737.71) 49(5022.32,3700.09) 50(4940.3,3709.35) 51(5019.41,3660.37) 52(4908.2,3710.21) 53(4985.15,3640.06) 54(4912.02,3678.32) 55(4968.09,3604.08) 56(4882.39,3690.73) 57(4928.81,3597.51) 58(4874.43,3659.61) 59(4899.9,3570.12) 60(4851.29,3681.88) 61(4860.9,3578.19) 62(4832.63,3655.74) 63(4824.04,3563.09) 64(4819.09,3684.86) 65(4790.59,3584.7) 66(4792.25,3667.22) 67(4750.77,3583.94) 68(4790.14,3699.27) 69(4727.39,3616.17) 70(4758.74,3692.53) 71(4689.98,3629.85) 72(4768.36,3723.17) 73(4679.82,3668.35) 74(4736.64,3728.22) 75(4649.88,3694.61)
  round 118.11 hole 118.11: Un1(4843.17,3769.49)

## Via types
v1: diameter 24, hole 8, F.CU to B.CU, tented both sides, 774 vias
v2: diameter 19.68, hole 7.87, F.CU to B.CU, tented both sides, 97 vias

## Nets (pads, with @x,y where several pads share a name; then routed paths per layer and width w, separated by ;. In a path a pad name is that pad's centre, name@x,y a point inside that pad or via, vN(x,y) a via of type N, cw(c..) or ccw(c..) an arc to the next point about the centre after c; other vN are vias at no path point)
1p66: R47.1 R64.1 U6.1 U6.4 | length 1555.6
  F.CU w20: R47.1@3028.47,4909.04 3028.47,4916.54 R47.1@3020.97,4916.54 3020.97,4874.9 3043.34,4852.53 3208.53,4852.53 v2(3210,4854) ; U6.4@3336.22,4715.29 3343.23,4715.29 3405.83,4777.9 3409.18,4777.9 3409.18,4815.82 U6.1@3411.02,4817.66 3411.02,4862.8 v2(3407.65,4866.18) ; v2(4076.45,4787.93) 4079.66,4784.73 4135.03,4784.73 4146.74,4796.44 R64.1@4146.74,4924.66
  B.CU w20: v2(3210,4854) 3222.18,4866.18 v2(3407.65,4866.18) 3488.44,4785.38 4073.9,4785.38 v2(4076.45,4787.93)
3v3: 3v3.1 C2.2 C4.2 C27.1 D10.1 R30.2 R74.2 U1.4 U2.5 U5.5 | length 10068.6
  F.CU w10: v2(3005.46,3441.74) 3044.73,3441.74 R30.2@3055.97,3452.98 3069.67,3466.68 3073.31,3466.68 3117.98,3511.35 C2.2@3118.96,3511.35 3159.53,3511.35 3170.04,3521.86 U1.4@3188.74,3521.86 ; C4.2@4079.1,3918.52 4082.86,3914.76 U2.5@4082.86,3858.25
  F.CU w20: U5.5@1395.9,2652.17 1395.9,2608.06 C27.1@1392.77,2604.93 1378.15,2590.3 1378.15,2502.03 3v3.1@1372.77,2496.66 1626.22,2243.22 1626.22,1882.5 1722.72,1786 3281.44,1786 v2(3283.32,1787.88) 3285.2,1786 4170.28,1786 v2(4758.58,2374.3) 5051.13,2666.85 5051.13,3405.1 5101,3454.97 5101,4199.28 5089.28,4211 4224,4211 4086,4073 4086,3925.42 C4.2@4079.1,3918.52 ; R74.2@4394.74,2675.31 4394.74,2629.91 v2(4404.58,2620.07)
  B.CU w10: v2(3005.46,3441.74) 3005.46,3106.56 3001.54,3102.64 3001.54,2770.09 3270.19,2501.43 3270.19,2091.52 3283.32,2078.4 v2(3283.32,1787.88)
  B.CU w20: v2(4404.58,2620.07) 4512.81,2620.07 v2(4758.58,2374.3)
3v3USB: C31.1 C33.2 C39.1 C54.1 J1/J3.1 R32.2 R41.2 R50.2 R51.2 R52.2 R63.2 R82.2 R89.2 U6.5 U7.5 U8.6 U10.5 U13.5 | length 11189.6
  F.CU w10: C39.1@2744.43,4985.88 2744.43,5021.38 U10.5@2769.98,5046.93 ; C54.1@3887.94,4977.14 3887.94,5034.37 U13.5@3889.78,5036.22 ; v2@4564.02,4860.82 v2(4563.18,4861.66) 4563.18,4901.59 C33.2@4564.82,4903.23 4587.77,4903.23 4602.31,4917.76 4602.31,4938.61 U8.6@4602.94,4939.25 ; U7.5@4654.41,4734.43 4736.99,4734.43 4737.47,4733.96 ; v2(4736.99,4860.82) v2@4737.47,4860.35 ; R50.2@4738.19,5358.68 R50.2@4738.69,5359.18
  F.CU w20: C39.1@2744.43,4985.88 2744.43,4847.8 2746.79,4845.44 v2(2746.79,4316.29) ; v2(2921.72,4304.64) 3268.64,4651.56 C31.1@3280.22,4651.56 ; R41.2@3019.75,5369.41 3058.15,5407.8 3374.45,5407.8 ; R82.2@3266.83,4960.92 3266.83,4958.12 3273.88,4951.08 3275.95,4953.15 3275.95,4961.66 3328.78,5014.49 3374.45,5014.49 ; C31.1@3280.22,4655.85 3398.49,4655.85 3410.2,4667.56 3410.2,4714.47 3424.88,4729.15 3478.1,4729.15 ; R63.2@3639.63,5407.8 3374.45,5407.8 ; C54.1@3885.44,4977.14 3637.45,4729.15 3478.1,4729.15 ; v2(4323.76,1836.21) 5128.87,2641.32 5128.87,4210.83 5100.83,4238.87 5016.13,4238.87 4926.76,4328.24 4926.76,4638 ; R52.2@4664.82,5297.51 4702.13,5297.51 ; R89.2@4737.47,4891.2 4737.47,4860.35 4737.47,4733.96 4737.47,4666.53 4766,4638 4926.76,4638 ; R50.2@4738.19,5358.68 4702.13,5322.62 4702.13,5297.51 ; 3374.45,5014.49 3478.1,4910.83 3478.1,4729.15 ; 3374.45,5014.49 3374.45,5407.8 ; 4702.13,5297.51 R51.2@4702.13,5237.48 4702.13,5192.7 4781.22,5113.6 4833.07,5113.6 4865.45,5113.6 4926.76,5052.29 4926.76,4638
  B.CU w10: v2(4563.18,4861.66) 4736.15,4861.66 v2(4736.99,4860.82)
  B.CU w20: v2(2746.79,4316.29) 2758.44,4304.64 4950.36,4304.64 v2(5016,4239) ; J1/J3.1@4062.78,2025 4251.57,1836.21 v2(4323.76,1836.21)
5v_led: 5V.1 C25.1 C26.1 C28.1 D1.2 D3.1 D9.1 L2.2 R80.1 U5.1 | length 1633.9
  F.CU w10: D9.1@1865.11,1975.99 1921,1975.99 2013,1883.99 2664.86,1883.99 2714.23,1933.36 2752.63,1933.36 R80.1@2803.34,1984.08
  F.CU w20: 5V.1@1717.36,2496.66 1810.34,2496.66 1865.11,2441.89 D9.1@1865.11,1996.25
  other v2: 1679.11,2646.71 1527.39,2774.93
5vUSB: D5.1 D9.2 J1/J3.21 K1.1 | length 6783.5
  F.CU w10: v2(1951,1996.5) 1951,2087 2161,2297 2161,2963.36 2227.52,3029.89 2227.52,5695.85 D5.1@2321.3,5789.63 2286.25,5824.68 2286.25,6003.29 2334.56,6051.6 K1.1@2334.56,6283.28
  F.CU w20: D9.2@1876.11,1872.99 1865.11,1883.99 1973.01,1883.99 2000,1857 3794.78,1857 J1/J3.21@3962.78,2025
  B.CU w10: v2(1951,1996.5) 1951,1884.5 v2(1953,1882.5)
ADC_Log: C9.1 J1/J3.6 R11.2 TP8.1 | length 1069.6
  F.CU w10: J1/J3.6@4062.78,2525 4168.75,2525 C9.1@4169.78,2523.97 4711.15,2523.97 4791.38,2604.2 4791.39,2671.6 4791.38,2797.48 ; R11.2@4769.42,2865.04 4783.12,2851.34 4785.53,2851.34 4791.38,2845.48 4791.38,2797.48 ; TP8.1@4825.03,2803.13 4819.39,2797.48 4791.38,2797.48
"ADC_Voltage sense": C17.1 J1/J3.25 R20.2 TP19.1 | length 295.9
  F.CU w10: TP19.1@3719.78,2358.55 3742.36,2381.13 R20.2@3742.36,2424.5 C17.1@3847.28,2424.5 3847.78,2425 J1/J3.25@3962.78,2425
AFEen: C67.1 R69.2 U3.14 | length 273.2
  F.CU w10: R69.2@4266.24,2961 4297.66,2961 C67.1@4329.9,2928.77 4338.66,2920.01 4463.79,2920.01 4467.13,2916.67 U3.14@4521.12,2916.67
